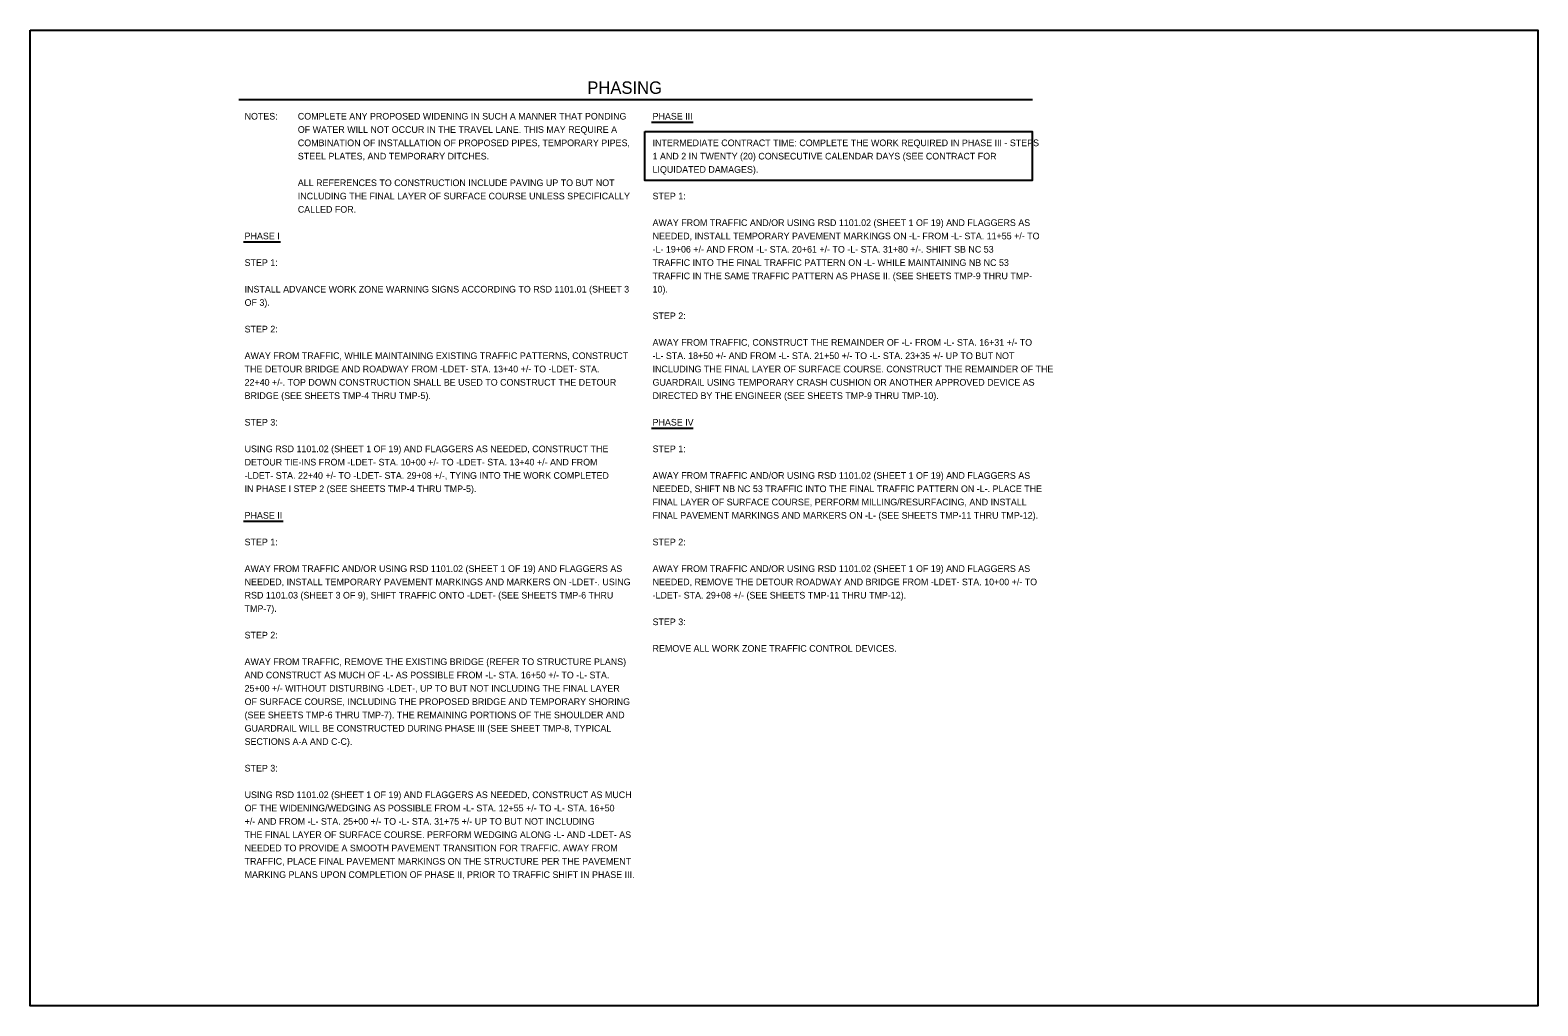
# Model space of a CAD drawing. Extents: x 0 to 1700, y 0 to 1100.
import ezdxf

# ---------------------------------------------------------------- set-up
doc = ezdxf.new("R2010")
doc.units = 0
for name, color, linetype in [('P_RDY_ROW_Permanent_Easement_CELL', 7, 'Continuous'), ('P_RDY_WCC_CELL', 7, 'Continuous'), ('Prop Grid Mask', 7, 'Continuous'), ('Sheet_Data_Field_CELL', 7, 'Continuous'), ('Sheet_Plan', 7, 'Continuous'), ('Sheet_RDY_XS_Number', 7, 'Continuous')]:
    doc.layers.add(name, color=color, linetype=linetype)

msp = doc.modelspace()

# ---------------------------------------------------------------- linework, layer by layer
at = {"layer": 'P_RDY_ROW_Permanent_Easement_CELL'}
msp.add_line((235.2, 1021.7), (1130.1, 1021.7), dxfattribs=at)
msp.add_lwpolyline([(693.1, 985.8), (1129.9, 985.8), (1129.9, 930.5), (693.1, 930.5)], close=True, dxfattribs=at)
at = {"layer": 'P_RDY_WCC_CELL'}
msp.add_lwpolyline([(693.1, 985.8), (1129.9, 985.8), (1129.9, 930.5), (693.1, 930.5)], close=True, dxfattribs=at)
at = {"layer": 'Sheet_Data_Field_CELL'}
msp.add_lwpolyline([(0, 1100), (1700, 1100), (1700, 0), (0, 0)], close=True, dxfattribs=at)
at = {"layer": 'Sheet_RDY_XS_Number'}
for p, q in [((700.5, 996.4), (747.6, 996.4)), ((240.5, 861.4), (282.4, 861.4)), ((700.5, 651.4), (747.6, 651.4)), ((240.5, 546.4), (285.4, 546.4))]:
    msp.add_line(p, q, dxfattribs=at)

# ---------------------------------------------------------------- texts
at = {"layer": 'Prop Grid Mask'}
for s, p in [('NOTES:', (241.8, 999.2)), ('COMPLETE ANY PROPOSED WIDENING IN SUCH A MANNER THAT PONDING ', (301.8, 999.2)), ('PHASE III', (701.8, 999.2)), ('OF WATER WILL NOT OCCUR IN THE TRAVEL LANE. THIS MAY REQUIRE A ', (301.8, 984.2)), ('COMBINATION OF INSTALLATION OF PROPOSED PIPES, TEMPORARY PIPES, ', (301.8, 969.2)), ('INTERMEDIATE CONTRACT TIME: COMPLETE THE WORK REQUIRED IN PHASE III - STEPS ', (701.8, 969.2)), ('STEEL PLATES, AND TEMPORARY DITCHES.', (301.8, 954.2)), ('1 AND 2 IN TWENTY (20) CONSECUTIVE CALENDAR DAYS (SEE CONTRACT FOR ', (701.8, 954.2)), ('LIQUIDATED DAMAGES).', (701.8, 939.2)), ('ALL REFERENCES TO CONSTRUCTION INCLUDE PAVING UP TO BUT NOT ', (301.8, 924.2)), ('CALLED FOR.', (301.8, 894.2)), ('INCLUDING THE FINAL LAYER OF SURFACE COURSE UNLESS SPECIFICALLY ', (301.8, 909.2)), ('STEP 1:', (701.8, 909.2)), ('AWAY FROM TRAFFIC AND/OR USING RSD 1101.02 (SHEET 1 OF 19) AND FLAGGERS AS ', (701.8, 879.2)), ('PHASE I', (241.8, 864.2)), ('NEEDED, INSTALL TEMPORARY PAVEMENT MARKINGS ON -L- FROM -L- STA. 11+55 +/- TO ', (701.8, 864.2)), ('-L- 19+06 +/- AND FROM -L- STA. 20+61 +/- TO -L- STA. 31+80 +/-. SHIFT SB NC 53 ', (701.8, 849.2)), ('STEP 1:', (241.8, 834.2)), ('TRAFFIC INTO THE FINAL TRAFFIC PATTERN ON -L- WHILE MAINTAINING NB NC 53 ', (701.8, 834.2)), ('TRAFFIC IN THE SAME TRAFFIC PATTERN AS PHASE II. (SEE SHEETS TMP-9 THRU TMP-', (701.8, 819.2)), ('INSTALL ADVANCE WORK ZONE WARNING SIGNS ACCORDING TO RSD 1101.01 (SHEET 3 ', (241.8, 804.2)), ('10).', (701.8, 804.2)), ('OF 3).', (241.8, 789.2)), ('STEP 2:', (241.8, 759.2)), ('STEP 2:', (701.8, 774.2)), ('AWAY FROM TRAFFIC, CONSTRUCT THE REMAINDER OF -L- FROM -L- STA. 16+31 +/- TO  ', (701.8, 744.2)), ('AWAY FROM TRAFFIC, WHILE MAINTAINING EXISTING TRAFFIC PATTERNS, CONSTRUCT ', (241.8, 729.2)), ('-L- STA. 18+50 +/- AND FROM -L- STA. 21+50 +/- TO -L- STA. 23+35 +/- UP TO BUT NOT ', (701.8, 729.2)), ('THE DETOUR BRIDGE AND ROADWAY FROM -LDET- STA. 13+40 +/- TO -LDET- STA.  ', (241.8, 714.2)), ('INCLUDING THE FINAL LAYER OF SURFACE COURSE. CONSTRUCT THE REMAINDER OF THE ', (701.8, 714.2)), ('22+40 +/-. TOP DOWN CONSTRUCTION SHALL BE USED TO CONSTRUCT THE DETOUR ', (241.8, 699.2)), ('GUARDRAIL USING TEMPORARY CRASH CUSHION OR ANOTHER APPROVED DEVICE AS ', (701.8, 699.2)), ('BRIDGE (SEE SHEETS TMP-4 THRU TMP-5).', (241.8, 684.2)), ('DIRECTED BY THE ENGINEER (SEE SHEETS TMP-9 THRU TMP-10).', (701.8, 684.2)), ('STEP 3:', (241.8, 654.2)), ('PHASE IV', (701.8, 654.2)), ('USING RSD 1101.02 (SHEET 1 OF 19) AND FLAGGERS AS NEEDED, CONSTRUCT THE ', (241.8, 624.2)), ('STEP 1:', (701.8, 624.2)), ('DETOUR TIE-INS FROM -LDET- STA. 10+00 +/- TO -LDET- STA. 13+40 +/- AND FROM           ', (241.8, 609.2)), ('-LDET- STA. 22+40 +/- TO -LDET- STA. 29+08 +/-, TYING INTO THE WORK COMPLETED ', (241.8, 594.2)), ('AWAY FROM TRAFFIC AND/OR USING RSD 1101.02 (SHEET 1 OF 19) AND FLAGGERS AS ', (701.8, 594.2)), ('IN PHASE I STEP 2 (SEE SHEETS TMP-4 THRU TMP-5).', (241.8, 579.2)), ('NEEDED, SHIFT NB NC 53 TRAFFIC INTO THE FINAL TRAFFIC PATTERN ON -L-. PLACE THE ', (701.8, 579.2)), ('FINAL LAYER OF SURFACE COURSE, PERFORM MILLING/RESURFACING, AND INSTALL ', (701.8, 564.2)), ('PHASE II', (241.8, 549.2)), ('FINAL PAVEMENT MARKINGS AND MARKERS ON -L- (SEE SHEETS TMP-11 THRU TMP-12).', (701.8, 549.2)), ('STEP 1:', (241.8, 519.2)), ('STEP 2:', (701.8, 519.2)), ('AWAY FROM TRAFFIC AND/OR USING RSD 1101.02 (SHEET 1 OF 19) AND FLAGGERS AS ', (241.8, 489.2)), ('AWAY FROM TRAFFIC AND/OR USING RSD 1101.02 (SHEET 1 OF 19) AND FLAGGERS AS ', (701.8, 489.2)), ('NEEDED, INSTALL TEMPORARY PAVEMENT MARKINGS AND MARKERS ON -LDET-. USING ', (241.8, 474.2)), ('NEEDED, REMOVE THE DETOUR ROADWAY AND BRIDGE FROM -LDET- STA. 10+00 +/- TO ', (701.8, 474.2)), ('RSD 1101.03 (SHEET 3 OF 9), SHIFT TRAFFIC ONTO -LDET- (SEE SHEETS TMP-6 THRU ', (241.8, 459.2)), ('-LDET- STA. 29+08 +/- (SEE SHEETS TMP-11 THRU TMP-12).', (701.8, 459.2)), ('TMP-7).', (241.8, 444.2)), ('STEP 3:', (701.8, 429.2)), ('STEP 2:', (241.8, 414.2)), ('AWAY FROM TRAFFIC, REMOVE THE EXISTING BRIDGE (REFER TO STRUCTURE PLANS) ', (241.8, 384.2)), ('REMOVE ALL WORK ZONE TRAFFIC CONTROL DEVICES.', (701.8, 399.2)), ('AND CONSTRUCT AS MUCH OF -L- AS POSSIBLE FROM -L- STA. 16+50 +/- TO -L- STA. ', (241.8, 369.2)), ('25+00 +/- WITHOUT DISTURBING -LDET-, UP TO BUT NOT INCLUDING THE FINAL LAYER ', (241.8, 354.2)), ('OF SURFACE COURSE, INCLUDING THE PROPOSED BRIDGE AND TEMPORARY SHORING ', (241.8, 339.2)), ('(SEE SHEETS TMP-6 THRU TMP-7). THE REMAINING PORTIONS OF THE SHOULDER AND ', (241.8, 324.2)), ('GUARDRAIL WILL BE CONSTRUCTED DURING PHASE III (SEE SHEET TMP-8, TYPICAL ', (241.8, 309.2)), ('SECTIONS A-A AND C-C).', (241.8, 294.2)), ('STEP 3:', (241.8, 264.2)), ('USING RSD 1101.02 (SHEET 1 OF 19) AND FLAGGERS AS NEEDED, CONSTRUCT AS MUCH ', (241.8, 234.2)), ('OF THE WIDENING/WEDGING AS POSSIBLE FROM -L- STA. 12+55 +/- TO -L- STA. 16+50 ', (241.8, 219.2)), ('+/- AND FROM -L- STA. 25+00 +/- TO -L- STA. 31+75 +/- UP TO BUT NOT INCLUDING ', (241.8, 204.2)), ('THE FINAL LAYER OF SURFACE COURSE. PERFORM WEDGING ALONG -L- AND -LDET- AS ', (241.8, 189.2)), ('NEEDED TO PROVIDE A SMOOTH PAVEMENT TRANSITION FOR TRAFFIC. AWAY FROM ', (241.8, 174.2)), ('TRAFFIC, PLACE FINAL PAVEMENT MARKINGS ON THE STRUCTURE PER THE PAVEMENT ', (241.8, 159.2)), ('MARKING PLANS UPON COMPLETION OF PHASE II, PRIOR TO TRAFFIC SHIFT IN PHASE III.', (241.8, 144.2))]:
    msp.add_text(s, height=7.5, dxfattribs=at).set_placement(p)
at = {"layer": 'Sheet_Plan'}
msp.add_text('PHASING', height=14, dxfattribs=at).set_placement((628.2, 1028.2))

doc.saveas('drawing.dxf')
